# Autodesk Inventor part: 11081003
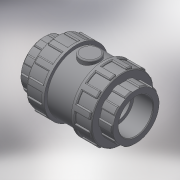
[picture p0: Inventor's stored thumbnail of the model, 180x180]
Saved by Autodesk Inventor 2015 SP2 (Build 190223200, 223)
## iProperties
Created: 2017-11
Part Number: 11081003
Material: Generic
Description: PLASSON CHECK VALVE THR 3/8" PTFE COATED SPRING + EPDM O-RING
Document SubType Name: Modeling
Designer: KIM
Density: 1 g/cm^3
Appearance: Default
Author: KIM
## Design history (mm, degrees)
derived "110810 - 110610 110910 - 110010.ipt"
feature "Solid1::110810 - 110610 110910 - 110010.ipt"
tag "TaggingFeature1"
body "Solid1"
other parameters: "d0" = 71, "d1" = 14.95, "d2" = 45, "d3" = 14, "d4" = 11.96, "d5" = 9.8, "d7" = 20.93, "d8" = 40.5, "d13" = 0.4485, "d23" = 14, "d24" = 43.2, "d25" = 0.299, "d26" = 0.4485, "d27" = 6.75, "d28" = 3.375, "d29" = 10.5, "d30" = 0, "d35" = 0.4485, "d39" = 22.5, "d45" = 360 deg, "d47" = 0.299, "d50" = 22.5, "d51" = 13.5, "d53" = 0, "d54" = 0.9, "d55" = 2.99, "d56" = 1.495, "d58" = 0, "d59" = 0.4485, "d61" = 360 deg, "G_" = 14.95, "l_" = 14, "H_" = 71, "K_" = 45
